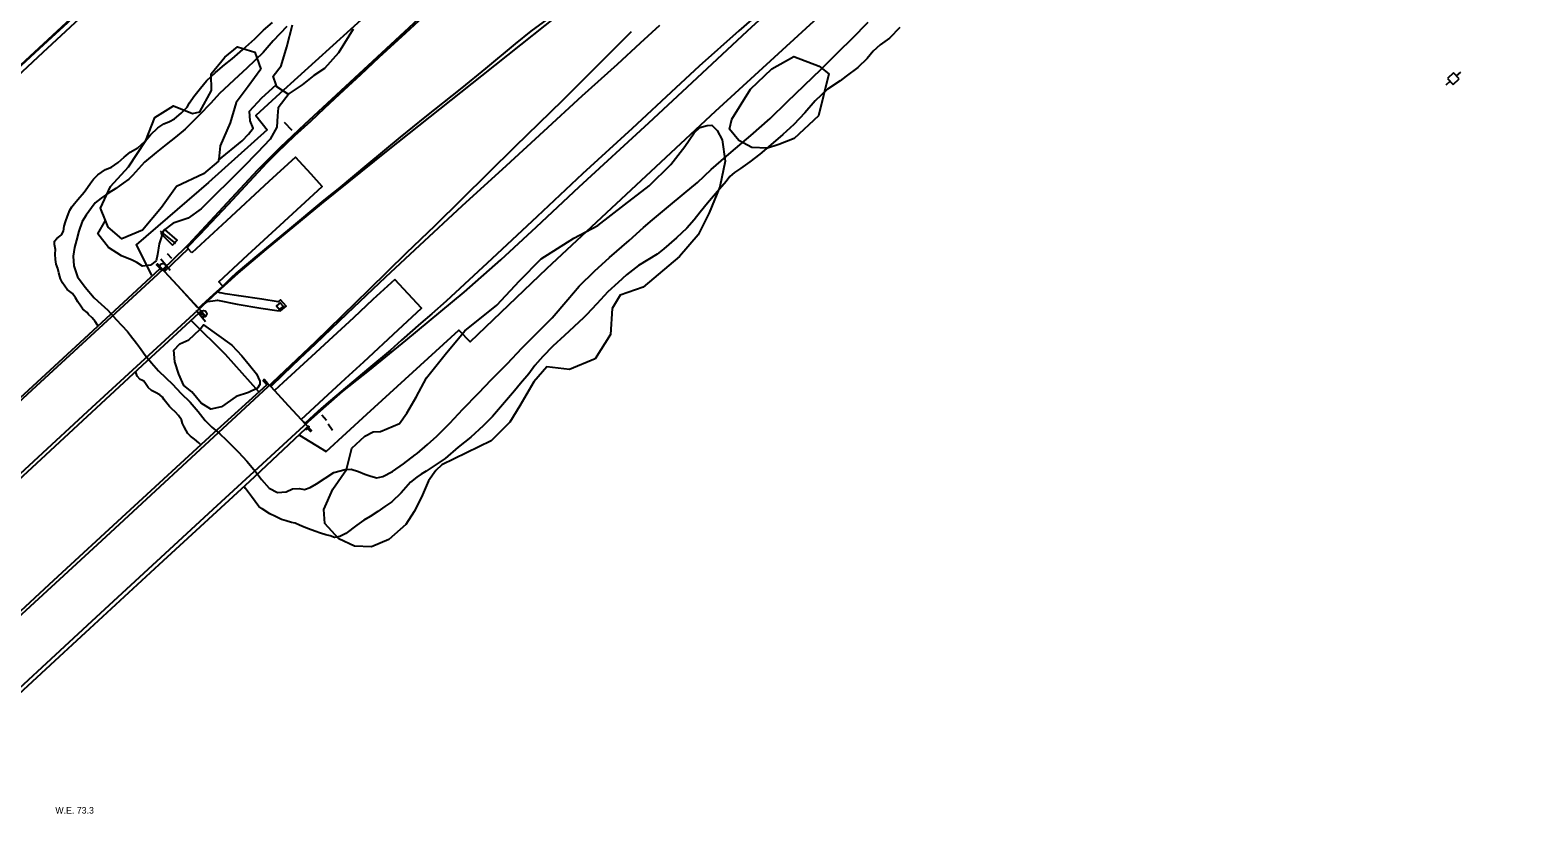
# Model space of a CAD drawing. Extents: x 2161152 to 2175754, y 602179 to 617749.
# Drawn here: x 2168307 to 2169226, y 609936 to 610417 of the extents above; entities that cross this region are included whole.
import ezdxf

# ---------------------------------------------------------------- set-up
doc = ezdxf.new("R2010")
doc.units = 0
for name, color, linetype in [('RD_EX_BldgApp_Sign', 7, 'Continuous'), ('RD_EX_Bridge', 7, 'Continuous'), ('RD_EX_Conc_Curb', 7, 'Continuous'), ('RD_EX_Conc_Slab', 7, 'Continuous'), ('RD_EX_DR_ErosCtrl', 7, 'Continuous'), ('RD_EX_DR_Inlet', 7, 'Continuous'), ('RD_EX_DR_Paved_Drainage', 7, 'Continuous'), ('RD_EX_Fence_ChLk', 7, 'Continuous'), ('RD_EX_GuardRail', 7, 'Continuous'), ('RD_EX_H2O', 7, 'Continuous'), ('RD_EX_H2O_txCode', 7, 'Continuous'), ('RD_EX_Road', 7, 'Continuous'), ('RD_EX_UT', 7, 'Continuous'), ('RD_EX_VEG', 7, 'Continuous'), ('RD_EX_WALL_Retaining', 7, 'Continuous')]:
    doc.layers.add(name, color=color, linetype=linetype)

msp = doc.modelspace()

# ---------------------------------------------------------------- linework, layer by layer
at = {"layer": 'RD_EX_BldgApp_Sign'}
for p, q in [((2168466.82, 610355.69), (2168462.15, 610360.56)), ((2168395.91, 610286.67), (2168386.61, 610294.19)), ((2168392.43, 610270.25), (2168386.69, 610277.18)), ((2168390.55, 610280.68), (2168393.24, 610277.71)), ((2168408.36, 610246), (2168414.07, 610239.03)), ((2168487.82, 610178.79), (2168484.9, 610182.08)), ((2168488.85, 610176.66), (2168491.38, 610172.92))]:
    msp.add_line(p, q, dxfattribs=at)
for centre in [(2168387.99, 610272.44), (2168412.79, 610243.78)]:
    msp.add_circle(centre, 2, dxfattribs=at)
at = {"layer": 'RD_EX_Bridge'}
for points in [[(2168293.03, 610382.93), (2168315.06, 610403.29), (2168337.27, 610423.92)], [(2168122.08, 610027.73), (2168176.05, 610077.46), (2168239.87, 610136.42), (2168303.61, 610195.11), (2168363.96, 610250.74), (2168386.33, 610271.35), (2168386.92, 610271.89), (2168388.62, 610269.98), (2168388.98, 610269.57), (2168409.72, 610247.16), (2168411.29, 610245.52), (2168409.89, 610244.23), (2168375.31, 610212.36), (2168308.13, 610149.9), (2168246.97, 610093.28), (2168181.48, 610032.91), (2168147.16, 610001.14), (2168084.65, 609943.37), (2168004.1, 609868.88)], [(2168102.05, 609878.54), (2168188.36, 609958.36), (2168255.34, 610020.04), (2168321.52, 610081.32), (2168365.61, 610121.96), (2168419.05, 610171.17), (2168451.34, 610200.56), (2168452.04, 610201.2), (2168453.74, 610199.42), (2168455.95, 610197.04), (2168464.43, 610187.89), (2168472.31, 610179.27), (2168474.56, 610176.98), (2168476.41, 610175.06), (2168475.63, 610174.33), (2168474.93, 610173.68), (2168440.73, 610141.63), (2168385.55, 610090.63), (2168324.9, 610034.67), (2168277.85, 609991.25), (2168213.23, 609931.55)]]:
    msp.add_lwpolyline(points, dxfattribs=at)
at = {"layer": 'RD_EX_Conc_Curb'}
for points in [[(2168290.51, 610385.59), (2168312.53, 610405.94), (2168334.75, 610426.57)], [(2168290.85, 610385.22), (2168312.87, 610405.57), (2168335.08, 610426.2)]]:
    msp.add_lwpolyline(points, dxfattribs=at)
at = {"layer": 'RD_EX_Conc_Slab'}
msp.add_lwpolyline([(2168393.86, 610285.75), (2168396.73, 610288.69), (2168389.25, 610295.17), (2168386.92, 610292.53), (2168393.86, 610285.75)], dxfattribs=at)
at = {"layer": 'RD_EX_DR_ErosCtrl'}
msp.add_lwpolyline([(2168463.5, 610419.02), (2168455.14, 610410.31), (2168449.12, 610403.24), (2168439.25, 610393.7), (2168431.4, 610386.59), (2168428.14, 610383.47), (2168422.5, 610378.11), (2168417.22, 610372.25), (2168410.19, 610365.03), (2168401.56, 610356.35), (2168395.81, 610351.58), (2168390.02, 610347.01), (2168383.91, 610342.12), (2168376.8, 610336.37), (2168369.45, 610328.21), (2168367.2, 610325.87), (2168363.9, 610323.4), (2168359.32, 610320.17), (2168355.09, 610317.63), (2168350.44, 610314.34), (2168346.81, 610311.43), (2168344.47, 610308.47), (2168341.36, 610303.97), (2168338.91, 610300.21), (2168336.85, 610294.17), (2168335.29, 610288.69), (2168334.18, 610284.16), (2168333.43, 610278.99), (2168333.73, 610273.06), (2168335.96, 610266.32), (2168340.68, 610260.03), (2168346.21, 610253.65), (2168350.45, 610249.7), (2168354.39, 610246.05), (2168359.6, 610240.39), (2168366.41, 610232.96), (2168368.33, 610230.59), (2168372.04, 610226.01), (2168373.79, 610223.37), (2168377.31, 610218.49), (2168381.09, 610213.86), (2168385.38, 610209.04), (2168389.78, 610204.79), (2168393.88, 610200.86), (2168398.88, 610195.5), (2168404.65, 610189.94), (2168409.55, 610184.14), (2168413.75, 610178.81), (2168417.81, 610174.72), (2168422.68, 610170.55), (2168426.68, 610166.95), (2168431.76, 610161.91), (2168434.06, 610159.41), (2168439.11, 610153.92), (2168444.38, 610147.55), (2168448.06, 610142.78), (2168452.73, 610137.41), (2168457.85, 610134.79), (2168463.23, 610135.33), (2168467.02, 610137.13), (2168471.07, 610137.25), (2168474.28, 610136.7), (2168477.81, 610137.82), (2168481.64, 610140.16), (2168487.02, 610143.64), (2168492.22, 610147.05), (2168499.04, 610148.9), (2168502.82, 610148.99), (2168507.26, 610147.68), (2168511.2, 610146.08), (2168514.73, 610144.8), (2168518.34, 610143.72), (2168522.09, 610144.66), (2168527.88, 610147.57), (2168534.6, 610152.29), (2168541.78, 610157.82), (2168542.91, 610158.72), (2168549.21, 610164.19), (2168554.93, 610169.23), (2168562.97, 610177.09), (2168570.75, 610185.69), (2168580.42, 610195.42), (2168588.31, 610203.66), (2168598.06, 610213.55), (2168606.81, 610222.81), (2168615.66, 610231.72), (2168625.34, 610241.44), (2168634.81, 610252.53), (2168641.65, 610260.65), (2168651.08, 610269.91), (2168660.29, 610278.23), (2168672.25, 610288.62), (2168680.91, 610296.55), (2168686.39, 610301.12), (2168696.22, 610309.21), (2168705.78, 610317.18), (2168713.86, 610323.82), (2168722.21, 610331.82), (2168734.29, 610342.33), (2168746.25, 610352.49), (2168758.22, 610362.96), (2168768.44, 610373), (2168778.8, 610383.03), (2168789.21, 610393.11), (2168800.08, 610403.88), (2168808.08, 610411.69), (2168817.9, 610421.72)], dxfattribs=at)
at = {"layer": 'RD_EX_DR_Inlet'}
msp.add_lwpolyline([(2168459.12, 610246.4), (2168461.47, 610248.32), (2168459.56, 610250.52), (2168457.24, 610248.62), (2168459.12, 610246.4)], dxfattribs=at)
at = {"layer": 'RD_EX_DR_Paved_Drainage'}
msp.add_lwpolyline([(2168414.02, 610251.11), (2168421.26, 610252.2), (2168433.23, 610249.79), (2168447.74, 610247.3), (2168457.47, 610245.89), (2168459.62, 610245.62), (2168463.06, 610248.42), (2168459.62, 610252.3), (2168458.37, 610251.04), (2168448.36, 610252.73), (2168434.32, 610254.78), (2168425.98, 610256.07), (2168424.16, 610256.4), (2168422.65, 610256.57), (2168420.91, 610257.44), (2168414.02, 610251.11)], dxfattribs=at)
at = {"layer": 'RD_EX_Fence_ChLk'}
for points in [[(2169019.88, 610894.6), (2169009.5, 610884.93), (2168934.44, 610815.43), (2168843.37, 610731.23), (2168775.6, 610668.45), (2168684.62, 610584.95), (2168594.72, 610501.7), (2168513.17, 610426.92), (2168459.24, 610378.07), (2168444.6, 610364.81), (2168451.53, 610356.01), (2168415.73, 610323.89), (2168371.76, 610285.83), (2168381.18, 610267.36)], [(2168471.38, 610169.71), (2168487.58, 610159.91), (2168512.33, 610182.53), (2168568.36, 610233.82), (2168575.32, 610226.74), (2168622.15, 610271.73), (2168724.77, 610367.31), (2168828.04, 610462.14), (2168943.49, 610569.3), (2169014.51, 610634.21), (2169119.93, 610731.91), (2169258.71, 610860.95)], [(2168405.56, 610239.6), (2168426.03, 610219.29), (2168446.37, 610196.5)]]:
    msp.add_lwpolyline(points, dxfattribs=at)
at = {"layer": 'RD_EX_GuardRail'}
for points in [[(2169141.63, 610976.85), (2169117.71, 610953.96), (2169103.98, 610940.9), (2169071.94, 610911.37), (2169030.65, 610873.27), (2168989.28, 610835.05), (2168957.13, 610805.46), (2168906.76, 610758.89), (2168839.36, 610696.61), (2168778.75, 610640.63), (2168716.78, 610583.63), (2168660.24, 610531.01), (2168614.63, 610489.38), (2168560.13, 610438.98), (2168474.33, 610359.24), (2168459.44, 610345.33), (2168445.57, 610331.16), (2168403.63, 610286.18), (2168393.09, 610275.66), (2168384.79, 610267.77), (2168308.26, 610197.15), (2168227.39, 610122.31)], [(2168189.16, 609912.65), (2168272.85, 609989.92), (2168347.55, 610059.04), (2168421.01, 610126.91), (2168476.57, 610177.9), (2168487.57, 610187.75), (2168497.53, 610196.48), (2168513.86, 610209.5), (2168536.19, 610227.59), (2168571.69, 610257.01), (2168594.06, 610276.7), (2168615.63, 610296.88), (2168641.68, 610321.18), (2168684.26, 610360.25), (2168710.55, 610384.85), (2168744.4, 610416.32), (2168808.46, 610475.42), (2168863.61, 610526.58), (2168925.4, 610583.4), (2168986.06, 610639.29), (2169003.31, 610655.04), (2169091.49, 610737.07), (2169219.61, 610854.87), (2169331.55, 610958.28)], [(2168041.76, 609907.19), (2168130.08, 609988.63), (2168199.59, 610052.92), (2168273.69, 610121.1), (2168344.84, 610186.89), (2168409.3, 610246.06), (2168421.34, 610257.12), (2168433.87, 610268.64), (2168451.03, 610283.02), (2168484.67, 610310.91), (2168525.28, 610343.55), (2168582.47, 610389), (2168644.84, 610438.82), (2168658.64, 610449.74), (2168698.6, 610480.37)], [(2168673.47, 610415.8), (2168631.48, 610373.92), (2168602.44, 610345.6), (2168553.74, 610297.55), (2168536.33, 610280.7), (2168513.46, 610258.4), (2168480.77, 610226.56), (2168454.7, 610201.65), (2168432.75, 610181.37), (2168353.16, 610107.79), (2168250.48, 610013.19), (2168172.06, 609940.44), (2168145.09, 609915.67)]]:
    msp.add_lwpolyline(points, dxfattribs=at)
at = {"layer": 'RD_EX_H2O'}
for points in [[(2168348.59, 610236.57), (2168348.28, 610236.91), (2168346.83, 610239.16), (2168345, 610241.34), (2168342.79, 610243.31), (2168341.81, 610244.62), (2168339.33, 610246.59), (2168337.94, 610248.44), (2168336.29, 610251.1), (2168334.81, 610253.63), (2168332.96, 610256.14), (2168331.27, 610257.5), (2168329.65, 610258.68), (2168328.36, 610260.62), (2168326.89, 610262.78), (2168325.59, 610265.05), (2168325.17, 610266.65), (2168324.53, 610268.8), (2168323.98, 610271.48), (2168323.03, 610274.14), (2168322.49, 610277.01), (2168322.44, 610280.21), (2168322.62, 610283.05), (2168321.98, 610286.06), (2168322.05, 610288.03), (2168323.3, 610289.79), (2168325.3, 610291.14), (2168326.18, 610292.01), (2168327.41, 610294.18), (2168327.77, 610297.24), (2168328.74, 610299.98), (2168329.92, 610303.31), (2168331.34, 610307.06), (2168332.54, 610308.98), (2168334.14, 610311.01), (2168336.27, 610313.57), (2168340.13, 610317.98), (2168342.16, 610320.87), (2168343.99, 610323.48), (2168345.75, 610325.95), (2168348.4, 610328.56), (2168353.03, 610331.87), (2168356.67, 610333.32), (2168360.83, 610336.02), (2168364.51, 610339.37), (2168368.16, 610342.46), (2168372.68, 610344.97), (2168377.31, 610349.11), (2168380.4, 610352.93), (2168384.95, 610357.15), (2168388.53, 610359.66), (2168391.96, 610361.03), (2168395.14, 610362.78), (2168399.24, 610366.08), (2168402.78, 610369.84), (2168404.33, 610372.38), (2168406.99, 610376.26), (2168411, 610381.38), (2168414.63, 610385.94), (2168420.11, 610391.02), (2168425.5, 610395.58), (2168430.27, 610399.35), (2168436.82, 610405.01), (2168444.04, 610411.56), (2168449.44, 610416.8), (2168454.83, 610421.47)], [(2168837.17, 610418.36), (2168830.94, 610411.97), (2168825.18, 610407.87), (2168820.97, 610404.02), (2168817.24, 610399.45), (2168811.55, 610394.11), (2168804.37, 610388.7), (2168800.85, 610385.94), (2168793.15, 610380.85), (2168785.49, 610373.7), (2168779.32, 610366.4), (2168772.5, 610359.19), (2168765.75, 610353.22), (2168758.52, 610346.81), (2168751.82, 610341.08), (2168745.81, 610336.41), (2168740.01, 610332.42), (2168736.31, 610329.99), (2168733.61, 610327.63), (2168731.34, 610324.6), (2168727.16, 610319.89), (2168719.9, 610311.33), (2168715.49, 610305.73), (2168711.76, 610301.16), (2168707.31, 610296.06), (2168701.05, 610290.15), (2168693.33, 610283.37), (2168689.25, 610280.16), (2168677.8, 610273.35), (2168670.65, 610267.52), (2168665.51, 610262.82), (2168659.19, 610257.13), (2168652.59, 610249.98), (2168646.17, 610243.22), (2168644.4, 610241.4), (2168632.89, 610230.53), (2168625.69, 610224.11), (2168619.55, 610217.78), (2168614.81, 610212.23), (2168611, 610207.27), (2168606.05, 610201.3), (2168602.24, 610196.81), (2168595.01, 610188.37), (2168588.84, 610181.23), (2168583.3, 610175.54), (2168575.7, 610168.64), (2168568.05, 610162.43), (2168560.07, 610155.51), (2168548.47, 610147.75), (2168545.42, 610146.06), (2168542.71, 610144.25), (2168539.02, 610141.16), (2168533.15, 610134.55), (2168527.57, 610129.13), (2168523.26, 610126.36), (2168518.98, 610123.16), (2168514.44, 610120.24), (2168510.52, 610118.01), (2168506.24, 610114.89), (2168499.57, 610109.8), (2168495.93, 610107.99), (2168492.69, 610107.44), (2168489.97, 610108.32), (2168487.32, 610109.12), (2168484.02, 610110.12), (2168480.63, 610111.2), (2168476.86, 610112.68), (2168474.1, 610113.6), (2168471.31, 610114.94), (2168468.67, 610116.06), (2168466.45, 610116.51), (2168463.1, 610117.55), (2168460.26, 610118.39), (2168456.73, 610120.1), (2168453.2, 610121.88), (2168448.58, 610124.92), (2168446.53, 610126.38), (2168441.94, 610132.38), (2168438.43, 610137.29), (2168437.48, 610138.62)], [(2168411.19, 610163.93), (2168409.91, 610165.11), (2168407.24, 610167.32), (2168404.89, 610169.15), (2168403.29, 610170.82), (2168402.31, 610172.6), (2168400.94, 610174.94), (2168400.02, 610176.89), (2168399.3, 610179.08), (2168397.47, 610181.81), (2168395.72, 610183.83), (2168393.38, 610186.09), (2168392.16, 610187.37), (2168388.84, 610191.41), (2168387.78, 610193), (2168386.13, 610194.32), (2168383.48, 610195.92), (2168381.15, 610196.96), (2168379.13, 610198.81), (2168377.4, 610201.32), (2168376.46, 610202.79), (2168375.19, 610203.44), (2168374.09, 610203.78), (2168372.31, 610205.86), (2168371.57, 610208.23), (2168371.41, 610208.73)]]:
    msp.add_lwpolyline(points, dxfattribs=at)
at = {"layer": 'RD_EX_Road'}
for points in [[(2168783.69, 610455.48), (2168739.03, 610416.47), (2168714.76, 610394.77), (2168700.71, 610381.62), (2168674, 610356.91), (2168643.72, 610329.11), (2168616.23, 610303.25), (2168588.43, 610277.26), (2168560.7, 610251.58), (2168551.96, 610243.7), (2168545.23, 610238.08), (2168533.48, 610227.69), (2168526.8, 610221.72), (2168513.48, 610210.6), (2168496.75, 610196.49), (2168488.95, 610189.84), (2168482.74, 610184.44), (2168474.56, 610176.98), (2168473.92, 610177.63), (2168472.31, 610179.27)], [(2168630.9, 610429.76), (2168612.32, 610416.16), (2168602.7, 610408.39), (2168584.73, 610393.38), (2168570.14, 610381.61), (2168547.69, 610363.71), (2168532.58, 610351.6), (2168512.26, 610334.7), (2168494.83, 610320.12), (2168489.17, 610315.53), (2168484.91, 610312.08), (2168465.29, 610295.62), (2168445.26, 610279.09), (2168432.69, 610268.54), (2168429.57, 610265.71), (2168424.5, 610260.74)], [(2168403.53, 610283.34), (2168402.93, 610284.41), (2168410.56, 610292.24), (2168427.98, 610310.76), (2168438.35, 610321.89), (2168451.53, 610336.02), (2168458.06, 610342.58), (2168462.93, 610347.33), (2168468.51, 610352.49), (2168478.1, 610361.31), (2168486.49, 610369.15), (2168495.78, 610377.93), (2168508.63, 610389.69), (2168519.93, 610400.25), (2168536.15, 610415.16), (2168549.27, 610427.32)], [(2168455.95, 610197.04), (2168453.74, 610199.42), (2168461.56, 610206.96), (2168471.44, 610216.48), (2168480.95, 610225.6), (2168500.35, 610244.05), (2168523.92, 610266.38), (2168544.66, 610285.61), (2168570.45, 610309.66), (2168597.41, 610334.33), (2168620.24, 610355.24), (2168643.57, 610376.65), (2168665.17, 610395.97), (2168679.16, 610409.11), (2168690.84, 610419.89)], [(2168405.68, 610281.05), (2168403.53, 610283.34), (2168388.98, 610269.57), (2168398.91, 610258.84), (2168408.81, 610248.14), (2168409.72, 610247.16), (2168413.96, 610251.06), (2168414.02, 610251.11), (2168420.91, 610257.44), (2168424.5, 610260.74), (2168422.04, 610263.37), (2168439.76, 610279.7), (2168459.51, 610297.89), (2168485, 610321.38), (2168478.33, 610328.89), (2168473.56, 610334.22), (2168468.81, 610339.4), (2168452.67, 610324.51), (2168426.8, 610300.59), (2168405.68, 610281.05)], [(2168529.36, 610264.83), (2168516.02, 610252.5), (2168504.17, 610241.46), (2168491.53, 610229.77), (2168478.53, 610217.73), (2168461.34, 610201.92), (2168455.95, 610197.04), (2168464.43, 610187.89), (2168464.59, 610187.72), (2168472.31, 610179.27), (2168483.28, 610189.45), (2168499.33, 610204.29), (2168510.45, 610214.57), (2168531.48, 610234.06), (2168545.56, 610247.23), (2168537.45, 610255.91), (2168529.36, 610264.83)]]:
    msp.add_lwpolyline(points, dxfattribs=at)
at = {"layer": 'RD_EX_UT'}
for p, q in [((2169172.62, 610385.64), (2169169.92, 610383.19)), ((2169174.63, 610390.76), (2169170.93, 610387.4)), ((2169170.93, 610387.4), (2169174.29, 610383.7)), ((2169174.29, 610383.7), (2169177.99, 610387.06)), ((2169177.99, 610387.06), (2169174.63, 610390.76)), ((2169178.81, 610391.26), (2169176.24, 610388.93))]:
    msp.add_line(p, q, dxfattribs=at)
at = {"layer": 'RD_EX_VEG'}
for points in [[(2168503.95, 610417.39), (2168495.08, 610402.88), (2168486.54, 610393.36), (2168480.12, 610389.16), (2168472.89, 610383.36), (2168464.96, 610378.19), (2168464.31, 610377.76), (2168457.4, 610382.31), (2168457.01, 610383.46), (2168455.28, 610388.66), (2168460.18, 610395.14), (2168463.6, 610406.66), (2168467.01, 610420.05)], [(2168447.67, 610392.92), (2168439.99, 610382.45), (2168432.7, 610372.67), (2168428.99, 610360.27), (2168422.87, 610346.26), (2168422.07, 610338.13), (2168422.02, 610337.61), (2168421.94, 610336.81), (2168412.74, 610329.14), (2168396.4, 610321.38), (2168387.11, 610308.63), (2168375.53, 610294.78), (2168363, 610289.46), (2168354.58, 610296.62), (2168353.04, 610300.62), (2168350.1, 610308.29), (2168356.18, 610321.5), (2168367.14, 610333.36), (2168377.71, 610349.52), (2168383.18, 610363.6), (2168394.53, 610370.6), (2168406.13, 610365.93), (2168410.53, 610367.02), (2168417.74, 610380.03), (2168417.43, 610390.12), (2168425.78, 610400.41), (2168433.52, 610406.56), (2168444.16, 610403.4), (2168447.67, 610392.92)], [(2168787.61, 610364.61), (2168772.76, 610350.77), (2168763.39, 610347.09), (2168756.42, 610344.9), (2168746.88, 610345.26), (2168738.96, 610349.58), (2168733.36, 610356.39), (2168734.74, 610362.44), (2168746.16, 610380.78), (2168759.15, 610393.21), (2168772.46, 610400.69), (2168788.05, 610394.92), (2168793.88, 610390.21), (2168787.61, 610364.61)], [(2168422.02, 610337.61), (2168436.29, 610349.27), (2168440.24, 610353.3), (2168443.1, 610356.96), (2168441.24, 610361.43), (2168440.78, 610367.43), (2168448.33, 610375.47), (2168457.01, 610383.46)], [(2168464.96, 610378.19), (2168458.34, 610369.52), (2168457.87, 610364.45), (2168457.54, 610357.67), (2168453.34, 610350.23), (2168445.44, 610342), (2168436.92, 610333.16), (2168411.46, 610307.74), (2168403.4, 610302.04), (2168394.36, 610299.06), (2168388.36, 610294.62), (2168385.74, 610286.51), (2168384.71, 610279.98), (2168383.87, 610276.07), (2168380.44, 610273.47), (2168375.52, 610272.93), (2168372.09, 610275.01), (2168369.31, 610276.43), (2168362.74, 610279.12), (2168354.91, 610284.35), (2168348.31, 610292.63), (2168353.04, 610300.62)], [(2168558, 610151.61), (2168554.37, 610148.27), (2168549.89, 610141.95), (2168545.54, 610132.05), (2168541.21, 610123.32), (2168536.06, 610115.42), (2168525.78, 610106.08), (2168515.23, 610101.78), (2168504.73, 610102.07), (2168495.3, 610106.49), (2168486.65, 610115.83), (2168486.18, 610124.45), (2168491.52, 610136.78), (2168499.85, 610148.82), (2168503.21, 610161.83), (2168511.03, 610169.28), (2168516.25, 610171.88), (2168520.64, 610171.96), (2168532.22, 610176.97), (2168536.62, 610183.26), (2168542.41, 610192.97), (2168548.73, 610204.77), (2168560.01, 610219.06), (2168572.14, 610233.43), (2168591.47, 610249.14), (2168605.3, 610263.98), (2168618.52, 610277.43), (2168638.55, 610289.96), (2168653.1, 610297.75), (2168669.33, 610310.35), (2168684.41, 610321.93), (2168697.55, 610334.83), (2168706.04, 610345.86), (2168711.9, 610354.24), (2168715.22, 610357.42), (2168719.79, 610358.75), (2168722.66, 610358.84), (2168725.77, 610355.59), (2168728.81, 610349.94), (2168730.62, 610337), (2168727.41, 610321.17), (2168720.94, 610305.34), (2168714.23, 610292.06), (2168702.87, 610278.77), (2168680.66, 610260.01), (2168666.64, 610255.24), (2168661.93, 610247.09), (2168660.73, 610231.11), (2168651.39, 610216.27), (2168635.82, 610209.94), (2168622.08, 610211.38), (2168614.04, 610202.36), (2168605.47, 610187.67), (2168599.52, 610177.64), (2168588.07, 610166.28), (2168558, 610151.61)], [(2168430.02, 610224.7), (2168436.16, 610218.1), (2168440.72, 610212.44), (2168445.02, 610207.18), (2168447.07, 610202.71), (2168447.03, 610200.79), (2168445.7, 610198.48), (2168440.12, 610195.91), (2168432.73, 610193.34), (2168423.68, 610187.13), (2168417.19, 610185.6), (2168411.42, 610189.39), (2168405.63, 610196.14), (2168400.73, 610199.99), (2168397.75, 610206.93), (2168395.31, 610214.47), (2168394.67, 610221.59), (2168398.3, 610225.5), (2168403.81, 610227.88), (2168410.56, 610234.33), (2168412.72, 610237.02), (2168430.02, 610224.7)]]:
    msp.add_lwpolyline(points, dxfattribs=at)
at = {"layer": 'RD_EX_WALL_Retaining'}
for points in [[(2168386.92, 610271.89), (2168384.73, 610274.26), (2168384.17, 610273.71), (2168386.33, 610271.35), (2168386.92, 610271.89)], [(2168411.29, 610245.52), (2168413.47, 610243.28), (2168412.87, 610242.75), (2168411.02, 610244.52), (2168410.29, 610243.78), (2168409.89, 610244.23), (2168411.29, 610245.52)], [(2168452.04, 610201.2), (2168449.8, 610203.68), (2168449.05, 610203), (2168451.34, 610200.56), (2168452.04, 610201.2)], [(2168476.41, 610175.06), (2168476.67, 610175.32), (2168477.08, 610174.9), (2168476.72, 610174.57), (2168478.58, 610172.56), (2168477.98, 610171.96), (2168476.13, 610173.94), (2168475.37, 610173.24), (2168474.93, 610173.68), (2168476.41, 610175.06)]]:
    msp.add_lwpolyline(points, dxfattribs=at)

# ---------------------------------------------------------------- texts
at = {"layer": 'RD_EX_H2O_txCode'}
msp.add_text('W.E. 73.3', height=4, dxfattribs=at).set_placement((2168322.49, 609939.02))

doc.saveas('drawing.dxf')
